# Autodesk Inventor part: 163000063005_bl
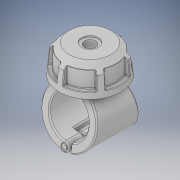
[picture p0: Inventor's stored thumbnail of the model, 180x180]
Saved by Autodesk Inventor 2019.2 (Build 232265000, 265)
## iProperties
Created: 2022-02
Part Number: 163000063005_bl
Material: Generic
Description: Plassadle Threaded 63x1/2''
Document SubType Name: Modeling
Designer: comp2
Density: 1 g/cm^3
Appearance: Default
Author: comp2
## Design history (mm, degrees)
derived "16300.ipt"
feature "Solid1::16300.ipt" dims "ScaleForDerivedMember" = 10
feature "Solid2::16300.ipt" dims "ScaleForDerivedMember" = 10
feature "Solid3::16300.ipt" dims "ScaleForDerivedMember" = 10
feature "Solid4::16300.ipt" dims "ScaleForDerivedMember" = 10
tag "TaggingFeature1"
body "Solid1"
body "Solid2"
body "Solid3"
body "Solid4"
other parameters: "d" = 63 [user parameter], "d1" = 25 [user parameter], "B" = 91 [user parameter], "L" = 89 [user parameter], "E_" = 54 [user parameter], "E1" = 102 [user parameter], "H1" = 136 [user parameter], "H2" = 49 [user parameter], "H3" = 78 [user parameter], "H_costum" = 49 [user parameter], "Rp" = 18.631 [user parameter], "d128" = 45.455 [user parameter], "d0" = 63 [user parameter], "d2" = 91 [user parameter], "d3" = 31.5 [user parameter], "d7" = 86.45 [user parameter], "d8" = 85 deg [user parameter], "d9" = 45 deg [user parameter], "d10" = 102 [user parameter], "d11" = 49 [user parameter], "d12" = 31.8185 [user parameter], "d13" = 42.84 [user parameter], "d14" = 27.9465 [user parameter], "d42" = 2.8 [user parameter], "d49" = 1.82 [user parameter], "d50" = 89 [user parameter], "d51" = 0 [user parameter], "d52" = 19.6 [user parameter], "d53" = 50.05 [user parameter], "d54" = 31.15 [user parameter], "d55" = 0 [user parameter], "d56" = 17.8 [user parameter], "d57" = 17.8 [user parameter], "d59" = 0 [user parameter], "d60" = 89 [user parameter], "d61" = 0 [user parameter], "d62" = 31.15 [user parameter], "d63" = 0 [user parameter], "d65" = 0 [user parameter], "d67" = 0 [user parameter], "d69" = 0 [user parameter], "d70" = 1 [user parameter], "d71" = 85.44 [user parameter], "d72" = 0 [user parameter], "d73" = 2 [user parameter], "d78" = 86.7 [user parameter], "d79" = 5.1 [user parameter], "d80" = 60 deg [user parameter], "d81" = 5.1 [user parameter], "d84" = 0 [user parameter], "d85" = 1 [user parameter], "d87" = 360 deg [user parameter], "d122" = 49 [user parameter], "d124" = 42.80128 [user parameter], "d125" = 2.27275 [user parameter], "d127" = 136 [user parameter], "d129" = 18.631 [user parameter], "d130" = 15.83635 [user parameter], "d131" = 31.85 [user parameter], "d132" = 45 deg [user parameter], "d133" = 22.295 [user parameter], "d134" = 9.3155 [user parameter], "d136" = 0 [user parameter], "d138" = 0 [user parameter]
